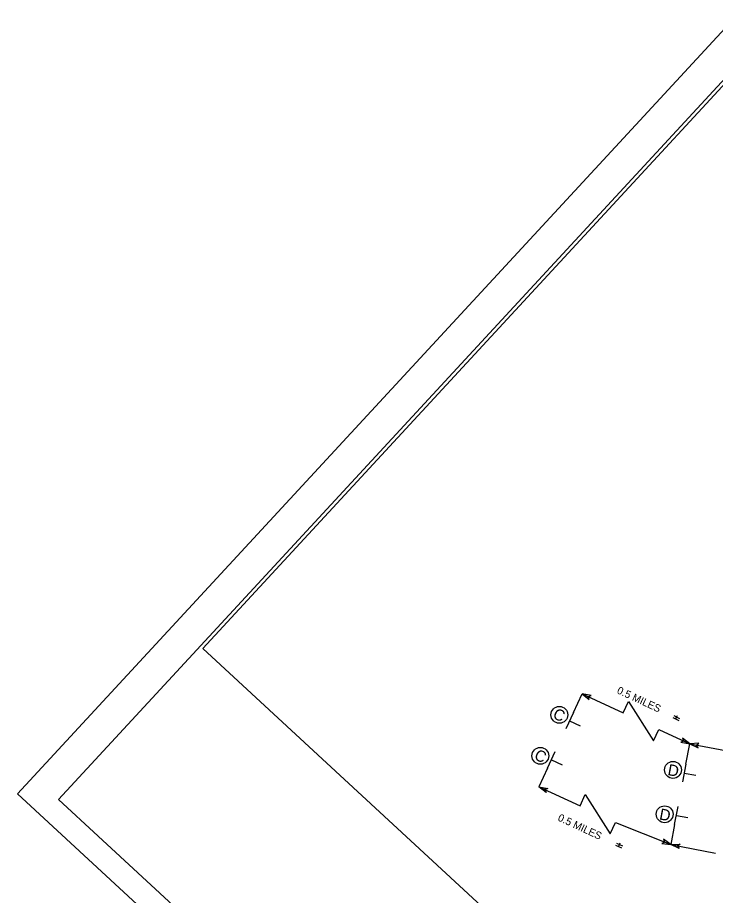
# Model space of a CAD drawing. Extents: x 1767460 to 1770129, y 996106 to 1001438.
# Drawn here: x 1767768 to 1768388, y 999850 to 1000630 of the extents above; entities that cross this region are included whole.
import ezdxf

# ---------------------------------------------------------------- set-up
doc = ezdxf.new("R2010")
doc.units = 0
for name, color, linetype in [('_CIVIL_CONSTRUCTION', 7, 'Continuous'), ('E_NCDOT_Terrain_Model_Contour_Minor', 7, 'Continuous'), ('E_NCDOT_Terrain_Model_Points_Low', 7, 'Continuous'), ('E_NCDOT_Terrain_Model_Triangle_Vertices', 7, 'Continuous'), ('E_NCDOT_Terrain_Model_Triangles', 7, 'Continuous'), ('P_NCDOT_Terrain_Points_High', 7, 'Continuous')]:
    doc.layers.add(name, color=color, linetype=linetype)

msp = doc.modelspace()

# ---------------------------------------------------------------- linework, layer by layer
at = {"layer": '_CIVIL_CONSTRUCTION'}
for centre in [(1768249.53, 1000010.58), (1768232.62, 999974.2), (1768350.54, 999961.67), (1768343.14, 999922.24)]:
    msp.add_circle(centre, 7.5, dxfattribs=at)
at = {"layer": 'E_NCDOT_Terrain_Model_Contour_Minor'}
msp.add_lwpolyline([(1768744.05, 999038.07), (1770128.77, 1000536.12), (1769152.55, 1001438.49), (1767767.83, 999940.44)], close=True, dxfattribs=at)
at = {"layer": 'E_NCDOT_Terrain_Model_Points_Low'}
msp.add_lwpolyline([(1767804.38, 999935.46), (1769171.05, 1001413.98), (1770107.33, 1000548.53), (1768740.66, 999070.01)], close=True, dxfattribs=at)
at = {"layer": 'E_NCDOT_Terrain_Model_Triangle_Vertices'}
for p, q in [((1768262.03, 1000012.76), (1768255.2, 999998.07)), ((1768258.59, 1000005.36), (1768268.11, 1000000.93)), ((1768239.01, 999963.24), (1768245.84, 999977.93)), ((1768242.45, 999970.65), (1768251.97, 999966.22)), ((1768362.11, 999966.87), (1768359.12, 999950.95)), ((1768360.61, 999958.84), (1768370.92, 999956.91)), ((1768352.03, 999913.2), (1768355.02, 999929.12)), ((1768353.54, 999921.22), (1768363.86, 999919.29))]:
    msp.add_line(p, q, dxfattribs=at)
msp.add_lwpolyline([(1769163.02, 1001400.87), (1767932.52, 1000069.67), (1768864.37, 999208.32), (1770094.87, 1000539.52)], close=True, dxfattribs=at)
at = {"layer": 'E_NCDOT_Terrain_Model_Triangles'}
for p, q in [((1768262.03, 1000012.76), (1768269.73, 1000029.34)), ((1768277.77, 1000027.79), (1768269.73, 1000029.34)), ((1768269.73, 1000029.34), (1768276.09, 1000024.19)), ((1768269.73, 1000029.34), (1768306.31, 1000012.33)), ((1768275.13, 1000026.83), (1768277.77, 1000027.79)), ((1768276.09, 1000024.19), (1768275.13, 1000026.83)), ((1768350.41, 1000008.11), (1768355.64, 1000005.68)), ((1768351.26, 1000009.93), (1768356.49, 1000007.5)), ((1768353.23, 1000007.33), (1768353.87, 1000008.72)), ((1768353.87, 1000008.72), (1768354.52, 1000010.1)), ((1768337.9, 999997.65), (1768365.49, 999984.83)), ((1768365.49, 999984.83), (1768359.12, 999989.98)), ((1768359.12, 999989.98), (1768360.09, 999987.34)), ((1768360.09, 999987.34), (1768357.45, 999986.38)), ((1768357.45, 999986.38), (1768365.49, 999984.83)), ((1768362.11, 999966.87), (1768365.49, 999984.83)), ((1768373.65, 999985.32), (1768365.49, 999984.83)), ((1768365.49, 999984.83), (1768372.92, 999981.41)), ((1768365.49, 999984.83), (1768405.13, 999977.38)), ((1768371.34, 999983.73), (1768373.65, 999985.32)), ((1768372.92, 999981.41), (1768371.34, 999983.73)), ((1768239.01, 999963.24), (1768231.31, 999946.67)), ((1768237.67, 999941.52), (1768231.31, 999946.67)), ((1768231.31, 999946.67), (1768239.34, 999945.12)), ((1768231.31, 999946.67), (1768267.89, 999929.67)), ((1768239.34, 999945.12), (1768236.71, 999944.16)), ((1768236.71, 999944.16), (1768237.67, 999941.52)), ((1768299.47, 999914.99), (1768348.66, 999895.24)), ((1768352.03, 999913.2), (1768348.66, 999895.24)), ((1768300.44, 999896.54), (1768305.67, 999894.11)), ((1768303.05, 999895.32), (1768303.7, 999896.71)), ((1768343.13, 999897.46), (1768340.55, 999896.35)), ((1768340.55, 999896.35), (1768348.66, 999895.24)), ((1768348.66, 999895.24), (1768342.03, 999900.04)), ((1768342.03, 999900.04), (1768343.13, 999897.46)), ((1768348.66, 999895.24), (1768356.83, 999895.72)), ((1768356.83, 999895.72), (1768354.51, 999894.14)), ((1768299.59, 999894.71), (1768304.82, 999892.29)), ((1768302.41, 999893.94), (1768303.05, 999895.32)), ((1768356.09, 999891.82), (1768348.66, 999895.24)), ((1768348.66, 999895.24), (1768388.31, 999887.79)), ((1768354.51, 999894.14), (1768356.09, 999891.82))]:
    msp.add_line(p, q, dxfattribs=at)
for points in [[(1768306.31, 1000012.33), (1768311.01, 1000022.44), (1768333.2, 999987.55), (1768337.9, 999997.65)], [(1768267.89, 999929.67), (1768272.59, 999939.77), (1768294.78, 999904.88), (1768299.47, 999914.99)]]:
    msp.add_lwpolyline(points, dxfattribs=at)
at = {"layer": 'P_NCDOT_Terrain_Points_High'}
msp.add_lwpolyline([(1769163.02, 1001400.87), (1767932.52, 1000069.67), (1768864.37, 999208.32), (1769639.43, 1000046.81), (1769513.61, 1000163.11), (1769964.83, 1000651.25), (1769968.19, 1000656.62)], close=True, dxfattribs=at)

# ---------------------------------------------------------------- texts
at = {"layer": '_CIVIL_CONSTRUCTION'}
for s, rotation, p in [('C', 335.07099, (1768242.95, 1000008.04)), ('C', 335.07099, (1768226.38, 999971.52)), ('D', 349.36227, (1768345.29, 999957.17)), ('D', 349.36227, (1768337.89, 999917.71))]:
    msp.add_text(s, height=10, rotation=rotation, dxfattribs=at).set_placement(p)
at = {"layer": 'E_NCDOT_Terrain_Model_Triangles'}
for p in [(1768300.13, 1000030.06), (1768247.54, 999916.92)]:
    msp.add_text('0.5 MILES', height=6.667, rotation=335.07099, dxfattribs=at).set_placement(p)

doc.saveas('drawing.dxf')
